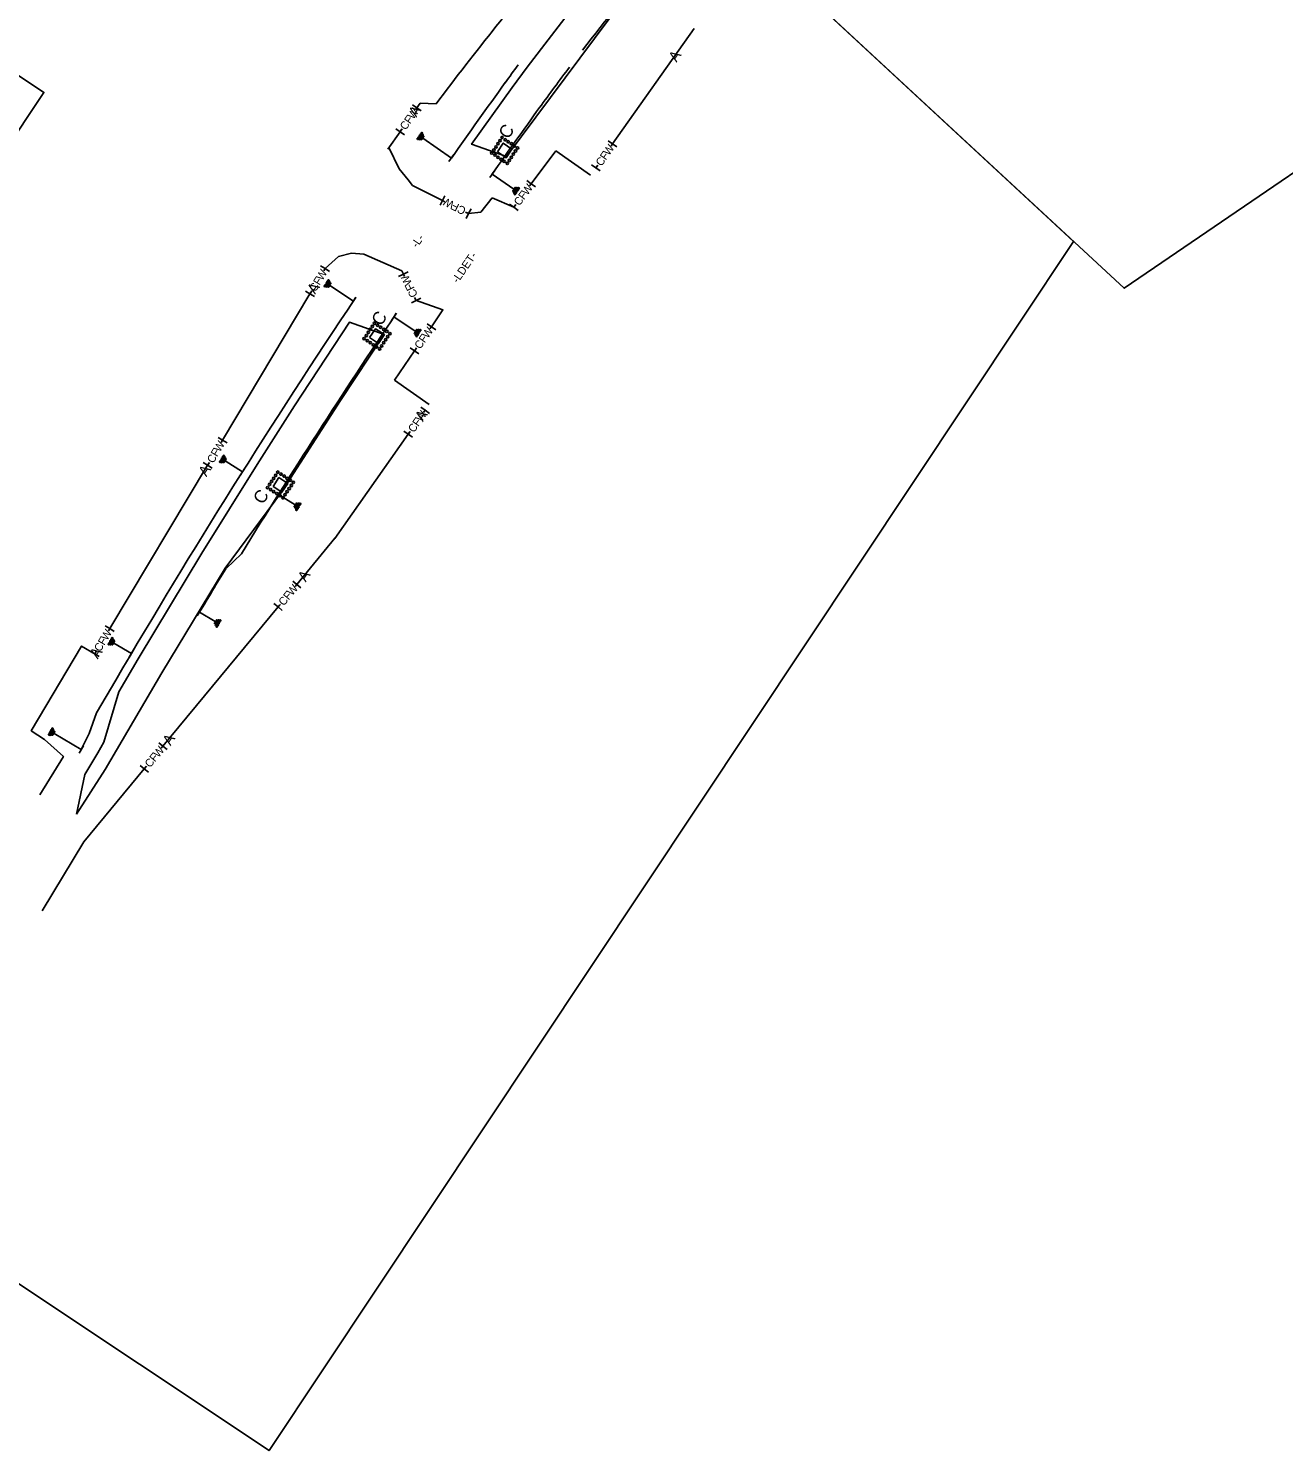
# Model space of a CAD drawing. Extents: x 2357856 to 2382083, y 331121 to 347536.
# Drawn here: x 2379985 to 2381167, y 331121 to 332460 of the extents above; entities that cross this region are included whole.
import ezdxf

# ---------------------------------------------------------------- set-up
doc = ezdxf.new("R2010")
doc.units = 0
for name, color, linetype in [('Coir Fiber Wattle Both CELL', 7, 'Continuous'), ('Default', 7, 'Continuous'), ('E_NCDOT_Vertical_Profile_Ground_Line', 7, 'Continuous'), ('Matting and PSRM Summary Sheet CELL', 7, 'Continuous'), ('Old_Level_12', 7, 'Continuous'), ('P_NCDOT_Horizontal_Alignment_Tick_Small', 7, 'Continuous'), ('Scratch_Level_6', 7, 'Continuous'), ('Scratch_Level_7', 7, 'Continuous'), ('Sheet Data Field CELL', 7, 'Continuous'), ('Sheet_Named_Boundary', 7, 'Continuous'), ('Sheet_Title_Data_Points_CELL', 7, 'Continuous')]:
    doc.layers.add(name, color=color, linetype=linetype)

msp = doc.modelspace()

# ---------------------------------------------------------------- linework, layer by layer
at = {"layer": 'Coir Fiber Wattle Both CELL'}
for p, q in [((2380185.4, 331965.1), (2380170.9, 331951)), ((2380067, 331846), (2380048.9, 331815.1)), ((2380048.9, 331815.1), (2380041.9, 331795.8)), ((2380041.9, 331795.8), (2380034.5, 331780.7))]:
    msp.add_line(p, q, dxfattribs=at)
for centre, radius, start, end in [((2382124.6, 331188.5), 2045, 139.2636, 142.294), ((2382124.6, 331188.5), 2085, 143.6143, 144.1843), ((2382124.6, 331188.5), 2045, 142.8535, 144.1843), ((2386191.3, 328253.9), 7100, 144.18428, 144.88815), ((2386191.3, 328253.9), 7060, 144.18428, 144.8082), ((2386191.3, 328253.9), 7100, 146.17166, 149.60684), ((2386191.3, 328253.9), 7060, 146.10116, 148.28685), ((2386191.3, 328253.9), 7065, 148.44639, 148.83551)]:
    msp.add_arc(centre, radius, start, end, dxfattribs=at)
at = {"layer": 'Default'}
for points in [[(2380245.4, 332929.7), (2381505.4, 333788.6), (2382082.8, 332941.6), (2381016.8, 332215)], [(2379358.1, 331688.3), (2380202.9, 332957.9), (2380245.4, 332929.7), (2380969.1, 332259.1), (2380211.5, 331120.5)]]:
    msp.add_lwpolyline(points, close=True, dxfattribs=at)
at = {"layer": 'Matting and PSRM Summary Sheet CELL'}
for p, q in [((2380350.7, 332385), (2380346.6, 332387.9)), ((2380349.3, 332383), (2380350.7, 332385)), ((2380350.7, 332385), (2380354.8, 332382.2)), ((2380334.9, 332362.5), (2380330.8, 332365.3)), ((2380334.9, 332362.5), (2380336.3, 332364.5)), ((2380334.9, 332362.5), (2380339, 332359.6)), ((2380335.3, 332363.1), (2380336.8, 332365.1)), ((2380535.1, 332350.9), (2380531, 332353.8)), ((2380533.7, 332348.9), (2380535.1, 332350.9)), ((2380535.1, 332350.9), (2380539.2, 332348.1)), ((2380519.2, 332328.4), (2380515.1, 332331.3)), ((2380519.2, 332328.4), (2380520.7, 332330.4)), ((2380519.2, 332328.4), (2380523.3, 332325.5)), ((2380519.7, 332329), (2380521.1, 332331.1)), ((2380458.4, 332313.5), (2380454.4, 332316.4)), ((2380456.9, 332311.4), (2380458.4, 332313.5)), ((2380458.4, 332313.5), (2380462.4, 332310.5)), ((2380374.8, 332297.7), (2380372.5, 332293.2)), ((2380374.8, 332297.7), (2380377, 332302.1)), ((2380377, 332296.5), (2380374.8, 332297.7)), ((2380398.7, 332285.7), (2380396.5, 332286.8)), ((2380399.4, 332285.3), (2380397.2, 332286.4)), ((2380399.4, 332285.3), (2380397.2, 332280.8)), ((2380399.4, 332285.3), (2380401.7, 332289.8)), ((2380442, 332291.3), (2380438, 332294.3)), ((2380442, 332291.3), (2380443.5, 332293.3)), ((2380442, 332291.3), (2380446, 332288.3)), ((2380442.5, 332291.9), (2380444, 332293.9)), ((2380264.2, 332233.5), (2380259.9, 332236.1)), ((2380262.9, 332231.3), (2380264.2, 332233.5)), ((2380264.2, 332233.5), (2380268.5, 332230.9)), ((2380338, 332228.3), (2380333.5, 332226.1)), ((2380338, 332228.3), (2380342.5, 332230.4)), ((2380339.1, 332226), (2380338, 332228.3)), ((2380250, 332209.9), (2380245.7, 332212.4)), ((2380250, 332209.9), (2380251.3, 332212)), ((2380250, 332209.9), (2380254.3, 332207.3)), ((2380250.4, 332210.5), (2380251.7, 332212.7)), ((2380350, 332203.4), (2380345.5, 332201.2)), ((2380349.7, 332204.1), (2380348.6, 332206.4)), ((2380350, 332203.4), (2380348.9, 332205.7)), ((2380350, 332203.4), (2380354.5, 332205.6)), ((2380364.4, 332178.8), (2380360.4, 332181.6)), ((2380363, 332176.7), (2380364.4, 332178.8)), ((2380364.4, 332178.8), (2380368.5, 332175.9)), ((2380348.6, 332156.2), (2380344.5, 332159.1)), ((2380348.6, 332156.2), (2380350, 332158.2)), ((2380348.6, 332156.2), (2380352.6, 332153.3)), ((2380349, 332156.8), (2380350.5, 332158.9)), ((2380358.4, 332100.1), (2380354.3, 332103)), ((2380356.9, 332098.1), (2380358.4, 332100.1)), ((2380358.4, 332100.1), (2380362.5, 332097.2)), ((2380167.7, 332072), (2380163.4, 332074.6)), ((2380166.4, 332069.9), (2380167.7, 332072)), ((2380167.7, 332072), (2380172, 332069.4)), ((2380342.5, 332077.6), (2380338.4, 332080.4)), ((2380342.5, 332077.6), (2380343.9, 332079.6)), ((2380342.5, 332077.6), (2380346.6, 332074.7)), ((2380343, 332078.2), (2380344.4, 332080.2)), ((2380153.6, 332048.3), (2380149.3, 332050.9)), ((2380153.6, 332048.3), (2380154.9, 332050.5)), ((2380153.6, 332048.3), (2380157.9, 332045.7)), ((2380154, 332049), (2380155.3, 332051.1)), ((2380237.5, 331936.1), (2380233.7, 331939.3)), ((2380235.9, 331934.2), (2380237.5, 331936.1)), ((2380237.5, 331936.1), (2380241.4, 331932.9)), ((2380219.9, 331914.9), (2380216.1, 331918.1)), ((2380219.9, 331914.9), (2380221.5, 331916.8)), ((2380219.9, 331914.9), (2380223.8, 331911.7)), ((2380220.5, 331915.5), (2380222.1, 331917.4)), ((2380061.4, 331894.5), (2380057.1, 331897)), ((2380060.1, 331892.3), (2380061.4, 331894.5)), ((2380061.4, 331894.5), (2380065.7, 331891.9)), ((2380047.2, 331870.8), (2380043, 331873.4)), ((2380047.2, 331870.8), (2380048.5, 331873)), ((2380047.2, 331870.8), (2380051.5, 331868.2)), ((2380047.7, 331871.5), (2380049, 331873.6)), ((2380111.5, 331783.8), (2380107.7, 331787)), ((2380109.9, 331781.8), (2380111.5, 331783.8)), ((2380111.5, 331783.8), (2380115.4, 331780.6)), ((2380093.9, 331762.5), (2380090.1, 331765.7)), ((2380093.9, 331762.5), (2380095.5, 331764.4)), ((2380093.9, 331762.5), (2380097.8, 331759.3)), ((2380094.5, 331763.1), (2380096.1, 331765))]:
    msp.add_line(p, q, dxfattribs=at)
at = {"layer": 'Old_Level_12'}
for p, q in [((2380356.4, 332356.4), (2380383.3, 332337.6)), ((2380385.6, 332340.9), (2380380.9, 332334.3)), ((2380419.3, 332319.3), (2380424, 332326)), ((2380441.9, 332308.5), (2380421.7, 332322.6)), ((2380268.7, 332217.8), (2380290.9, 332203)), ((2380293.2, 332206.4), (2380288.7, 332199.6)), ((2380326.8, 332184.7), (2380331.4, 332191.5)), ((2380349.1, 332174.7), (2380329.1, 332188.1)), ((2380170.2, 332052.5), (2380186.5, 332042.3)), ((2380188.6, 332045.7), (2380184.3, 332038.8)), ((2380218.1, 332017.5), (2380222.5, 332024.4)), ((2380236, 332011.1), (2380220.3, 332020.9)), ((2380143.6, 331906.5), (2380147.8, 331913.5)), ((2380160.8, 331901.2), (2380145.9, 331910)), ((2380065.2, 331880.9), (2380081.8, 331871.1)), ((2380083.9, 331874.6), (2380079.8, 331867.6)), ((2380008.9, 331795.7), (2380034.5, 331780.7)), ((2380036.7, 331784.2), (2380032.6, 331777.1))]:
    msp.add_line(p, q, dxfattribs=at)
for centre, major_axis in [((2380351.7, 332355.8), (0.613, -0.43)), ((2380352.6, 332357), (0.613, -0.43)), ((2380353.3, 332355.6), (0.613, -0.43)), ((2380353.5, 332358.5), (0.613, -0.43)), ((2380354.2, 332357.1), (0.613, -0.43)), ((2380354.4, 332359.8), (0.613, -0.43)), ((2380354.9, 332355.6), (0.613, -0.43)), ((2380355, 332358.3), (0.613, -0.43)), ((2380355.3, 332361.1), (0.613, -0.43)), ((2380355.8, 332356.9), (0.613, -0.43)), ((2380355.9, 332359.6), (0.613, -0.43)), ((2380356.6, 332358.1), (0.613, -0.43)), ((2380442.5, 332308.1), (-0.613, 0.431)), ((2380443.3, 332309.3), (-0.613, 0.431)), ((2380444.1, 332307.8), (-0.613, 0.431)), ((2380444.9, 332309.3), (-0.613, 0.431)), ((2380445.7, 332307.9), (-0.613, 0.431)), ((2380446.5, 332309.1), (-0.613, 0.431)), ((2380441.7, 332306.8), (-0.613, 0.431)), ((2380442.3, 332305.3), (-0.613, 0.431)), ((2380443, 332303.8), (-0.613, 0.431)), ((2380443.2, 332306.6), (-0.613, 0.431)), ((2380443.9, 332305.1), (-0.613, 0.431)), ((2380444.7, 332306.4), (-0.613, 0.431)), ((2380264.1, 332217), (0.624, -0.415)), ((2380264.9, 332218.3), (0.624, -0.415)), ((2380265.7, 332216.9), (0.624, -0.415)), ((2380265.8, 332219.8), (0.624, -0.415)), ((2380266.5, 332218.4), (0.624, -0.415)), ((2380266.6, 332221.1), (0.624, -0.415)), ((2380267.3, 332216.9), (0.624, -0.415)), ((2380267.3, 332219.6), (0.624, -0.415)), ((2380267.5, 332222.4), (0.624, -0.415)), ((2380268.2, 332220.9), (0.624, -0.415)), ((2380268.1, 332218.2), (0.624, -0.415)), ((2380268.9, 332219.5), (0.624, -0.415)), ((2380349.7, 332174.3), (-0.623, 0.416)), ((2380350.6, 332175.6), (-0.623, 0.416)), ((2380351.3, 332174.1), (-0.623, 0.416)), ((2380352.2, 332175.6), (-0.623, 0.416)), ((2380352.9, 332174.3), (-0.623, 0.416)), ((2380353.8, 332175.5), (-0.623, 0.416)), ((2380349, 332173.1), (-0.623, 0.416)), ((2380349.6, 332171.6), (-0.623, 0.416)), ((2380350.3, 332170.1), (-0.623, 0.416)), ((2380350.5, 332172.9), (-0.623, 0.416)), ((2380351.2, 332171.4), (-0.623, 0.416)), ((2380352, 332172.7), (-0.623, 0.416)), ((2380167.2, 332054.5), (0.634, -0.4)), ((2380168, 332055.8), (0.634, -0.4)), ((2380168.7, 332054.3), (0.634, -0.4)), ((2380168.8, 332057.1), (0.634, -0.4)), ((2380169.6, 332055.6), (0.634, -0.4)), ((2380170.3, 332054.2), (0.634, -0.4)), ((2380165.5, 332051.6), (0.634, -0.4)), ((2380166.4, 332052.9), (0.634, -0.4)), ((2380167.1, 332051.5), (0.634, -0.4)), ((2380167.9, 332053.1), (0.634, -0.4)), ((2380168.7, 332051.6), (0.634, -0.4)), ((2380169.5, 332052.9), (0.634, -0.4)), ((2380235.9, 332009.4), (-0.634, 0.398)), ((2380236.6, 332010.7), (-0.634, 0.398)), ((2380236.6, 332008), (-0.634, 0.398)), ((2380237.3, 332006.5), (-0.634, 0.398)), ((2380237.4, 332012), (-0.634, 0.398)), ((2380237.5, 332009.3), (-0.634, 0.398)), ((2380238.2, 332007.8), (-0.634, 0.398)), ((2380238.2, 332010.5), (-0.634, 0.398)), ((2380239, 332012.1), (-0.634, 0.398)), ((2380239, 332009.1), (-0.634, 0.398)), ((2380239.8, 332010.7), (-0.634, 0.398)), ((2380240.6, 332012), (-0.634, 0.398)), ((2380160.7, 331899.5), (-0.645, 0.381)), ((2380161.4, 331900.8), (-0.645, 0.381)), ((2380161.5, 331898.1), (-0.645, 0.381)), ((2380162.2, 331902.1), (-0.645, 0.381)), ((2380162.2, 331896.6), (-0.645, 0.381)), ((2380162.3, 331899.4), (-0.645, 0.381)), ((2380163, 331900.7), (-0.645, 0.381)), ((2380163, 331898), (-0.645, 0.381)), ((2380163.8, 331902.2), (-0.645, 0.381)), ((2380163.8, 331899.3), (-0.645, 0.381)), ((2380164.6, 331900.9), (-0.645, 0.381)), ((2380165.4, 331902.2), (-0.645, 0.381)), ((2380060.6, 331879.8), (0.645, -0.38)), ((2380061.4, 331881.2), (0.645, -0.38)), ((2380062.2, 331882.7), (0.645, -0.38)), ((2380062.2, 331879.8), (0.645, -0.38)), ((2380063, 331884.1), (0.645, -0.38)), ((2380063, 331881.4), (0.645, -0.38)), ((2380063.8, 331885.4), (0.645, -0.38)), ((2380063.7, 331882.6), (0.645, -0.38)), ((2380063.8, 331879.9), (0.645, -0.38)), ((2380064.5, 331884), (0.645, -0.38)), ((2380064.6, 331881.3), (0.645, -0.38)), ((2380065.3, 331882.6), (0.645, -0.38)), ((2380006.6, 331798.9), (0.645, -0.38)), ((2380007.4, 331800.3), (0.645, -0.38)), ((2380008.2, 331798.9), (0.645, -0.38)), ((2380004.3, 331794.7), (0.645, -0.38)), ((2380005.1, 331796), (0.645, -0.38)), ((2380005.8, 331797.6), (0.645, -0.38)), ((2380005.9, 331794.7), (0.645, -0.38)), ((2380006.6, 331796.2), (0.645, -0.38)), ((2380007.4, 331797.5), (0.645, -0.38)), ((2380007.5, 331794.8), (0.645, -0.38)), ((2380008.2, 331796.1), (0.645, -0.38)), ((2380008.9, 331797.4), (0.645, -0.38))]:
    msp.add_ellipse(centre, major_axis=major_axis, ratio=0.927398, dxfattribs=at)
at = {"layer": 'Scratch_Level_6'}
for p, q in [((2380431.6, 332357.8), (2380431.5, 332357.8)), ((2380434.5, 332355.9), (2380434.4, 332355.9)), ((2380437.4, 332353.9), (2380437.4, 332354)), ((2380311.4, 332183), (2380311.3, 332183.1)), ((2380314.3, 332181.1), (2380314.2, 332181.1)), ((2380317.2, 332179.2), (2380317.1, 332179.2)), ((2380220.4, 332042.8), (2380220.3, 332042.9)), ((2380223.3, 332040.9), (2380223.2, 332041)), ((2380226.2, 332039), (2380226.2, 332039))]:
    msp.add_line(p, q, dxfattribs=at)
for points in [[(2380426.5, 332343.4), (2380432, 332351.7), (2380440.3, 332346.1), (2380434.8, 332337.8)], [(2380306.2, 332168.6), (2380311.8, 332176.9), (2380320.1, 332171.4), (2380314.5, 332163.1)], [(2380215.3, 332028.4), (2380220.8, 332036.7), (2380229.1, 332031.2), (2380223.6, 332022.9)]]:
    msp.add_lwpolyline(points, close=True, dxfattribs=at)
for centre in [(2380425.1, 332348.1), (2380427.1, 332351.1), (2380429, 332354), (2380439.7, 332351.1), (2380442.6, 332349.1), (2380421.2, 332342.3), (2380423.2, 332345.2), (2380424.2, 332340.4), (2380427.1, 332338.4), (2380430, 332336.5), (2380432.9, 332334.6), (2380437.8, 332335.5), (2380439.7, 332338.4), (2380441.6, 332341.4), (2380443.6, 332344.3), (2380445.5, 332347.2), (2380435.8, 332332.6), (2380304.9, 332173.4), (2380306.8, 332176.3), (2380308.8, 332179.2), (2380319.5, 332176.3), (2380322.4, 332174.4), (2380301, 332167.6), (2380303, 332170.5), (2380303.9, 332165.6), (2380306.8, 332163.7), (2380309.8, 332161.7), (2380317.5, 332160.8), (2380319.5, 332163.7), (2380321.4, 332166.6), (2380323.3, 332169.5), (2380325.3, 332172.4), (2380312.7, 332159.8), (2380315.6, 332157.9), (2380210, 332027.4), (2380212, 332030.3), (2380213.9, 332033.2), (2380215.9, 332036.1), (2380217.8, 332039), (2380228.5, 332036.1), (2380230.4, 332026.4), (2380231.4, 332034.2), (2380232.4, 332029.3), (2380234.3, 332032.2), (2380213, 332025.4), (2380215.9, 332023.5), (2380218.8, 332021.6), (2380221.7, 332019.6), (2380224.6, 332017.7), (2380226.6, 332020.6), (2380228.5, 332023.5)]:
    msp.add_circle(centre, 1.12, dxfattribs=at)
for centre, start, end in [((2380430.9, 332356.9), 58.8724, 53.8495), ((2380433.9, 332354.9), 58.5359, 54.186), ((2380436.8, 332353), 58.1368, 54.5852), ((2380310.7, 332182.1), 58.8724, 53.8495), ((2380313.6, 332180.2), 58.5359, 54.186), ((2380316.5, 332178.3), 58.1368, 54.5852), ((2380219.7, 332041.9), 58.8724, 53.8495), ((2380222.7, 332040), 58.5359, 54.186), ((2380225.6, 332038.1), 58.1368, 54.5852)]:
    msp.add_arc(centre, 1.12, start, end, dxfattribs=at)
at = {"layer": 'Scratch_Level_7'}
msp.add_lwpolyline([(2379956.4, 332428.1), (2379762.4, 332136.6), (2379805.4, 332108), (2379999.4, 332399.5)], close=True, dxfattribs=at)
at = {"layer": 'Sheet Data Field CELL'}
msp.add_lwpolyline([(2380503.7, 332487.2), (2380454.6, 332423.4), (2380440.4, 332404), (2380402.2, 332350.6), (2380435.1, 332339), (2380531.8, 332468.7)], dxfattribs=at)
msp.add_lwpolyline([(2380030, 331719.7), (2380038, 331757), (2380050.2, 331777.7), (2380055.9, 331787.5), (2380069.9, 331835), (2380088.2, 331866.1), (2380148.1, 331965.6), (2380200.3, 332049.1), (2380235.5, 332104.2), (2380287.2, 332183), (2380319.8, 332171.5), (2380278.9, 332109.5), (2380223.3, 332022.9), (2380170, 331951.5), (2380110.5, 331852.8), (2380057.1, 331761.8)], close=True, dxfattribs=at)
at = {"layer": 'Sheet_Named_Boundary'}
for p, q in [((2380535.1, 332350.9), (2380611.8, 332459.7)), ((2380353.7, 332389.3), (2380350.7, 332385)), ((2380368.9, 332388.7), (2380353.7, 332389.3)), ((2380334.9, 332362.5), (2380323.4, 332346.1)), ((2380481.5, 332344.4), (2380458.4, 332313.5)), ((2380481.5, 332344.4), (2380514.3, 332321.4)), ((2380374.8, 332297.7), (2380346.5, 332311.8)), ((2380442, 332291.3), (2380421.7, 332300.3)), ((2380167.7, 332072), (2380250, 332209.9)), ((2380329.6, 332128.6), (2380348.6, 332156.2)), ((2380362.3, 332105.7), (2380329.6, 332128.6)), ((2380273.4, 331979.5), (2380342.5, 332077.6)), ((2380061.4, 331894.5), (2380153.6, 332048.3)), ((2380237.5, 331936.1), (2380273.4, 331979.6)), ((2380111.5, 331783.8), (2380219.9, 331914.9))]:
    msp.add_line(p, q, dxfattribs=at)
for points in [[(2380324.3, 332347.5), (2380334, 332327.4), (2380342.6, 332317.1), (2380346.5, 332311.8)], [(2380399.4, 332285.3), (2380410.9, 332286.8), (2380421.7, 332300.3)], [(2380338, 332228.3), (2380336.4, 332231.5), (2380300.6, 332247.3), (2380289.2, 332248), (2380277, 332244.9), (2380264.2, 332233.5)], [(2380364.4, 332178.8), (2380375.3, 332194.6), (2380349.3, 332203.7)], [(2379995.5, 331738.1), (2380017.7, 331774.2), (2379999.8, 331790.2), (2379987.5, 331798.4), (2380034.9, 331878.1), (2380047.6, 331870.6)], [(2379997.8, 331628.9), (2380037, 331693.6), (2380093.9, 331762.5)]]:
    msp.add_lwpolyline(points, dxfattribs=at)
for centre, radius, start, end in [((2382983.2, 330424), 3270.3, 139.851, 143.0741), ((2380368.9, 332388.7), 0.0000000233, 179.7652, 180.1182)]:
    msp.add_arc(centre, radius, start, end, dxfattribs=at)

# ---------------------------------------------------------------- texts
at = {"layer": 'E_NCDOT_Vertical_Profile_Ground_Line'}
for p in [(2380436.7, 332354.7), (2380316.9, 332178.7), (2380205.5, 332010.7)]:
    msp.add_text('C', height=12, rotation=56.361, dxfattribs=at).set_placement(p)
at = {"layer": 'Matting and PSRM Summary Sheet CELL'}
for s, rotation, p in [('F', 54.9145, (2380344.3, 332369.2)), ('W', 54.9145, (2380347.4, 332373.5)), ('C', 54.9145, (2380340.2, 332363.4)), ('W', 54.829, (2380531.7, 332339.4)), ('C', 54.829, (2380524.6, 332329.3)), ('F', 54.829, (2380528.7, 332335.1)), ('W', 53.3883, (2380454.8, 332302)), ('W', 153.3742, (2380386.7, 332296)), ('C', 53.3883, (2380447.4, 332292.1)), ('F', 53.3883, (2380451.6, 332297.8)), ('F', 153.3742, (2380391.3, 332293.7)), ('C', 153.3742, (2380397.7, 332290.5)), ('W', 58.9143, (2380261.7, 332221.7)), ('C', 58.9143, (2380255.3, 332211.1)), ('F', 58.9143, (2380259, 332217.3)), ('W', 115.8148, (2380346.4, 332219.7)), ('F', 115.8148, (2380348.7, 332215)), ('C', 115.8148, (2380351.8, 332208.6)), ('W', 54.829, (2380361.1, 332167.2)), ('C', 54.829, (2380353.9, 332157.1)), ('F', 54.829, (2380358, 332163)), ('W', 54.829, (2380355, 332088.6)), ('C', 54.829, (2380347.9, 332078.5)), ('F', 54.829, (2380352, 332084.3)), ('W', 59.2049, (2380165.2, 332060.2)), ('C', 59.2049, (2380158.9, 332049.6)), ('F', 59.2049, (2380162.5, 332055.8)), ('W', 50.4117, (2380233.3, 331924.9)), ('C', 50.4117, (2380225.4, 331915.4)), ('F', 50.4117, (2380229.9, 331920.9)), ('W', 59.096, (2380058.9, 331882.7)), ('C', 59.096, (2380052.5, 331872.1)), ('F', 59.096, (2380056.2, 331878.2)), ('F', 50.4117, (2380103.9, 331768.5)), ('W', 50.4117, (2380107.3, 331772.5)), ('C', 50.4117, (2380099.4, 331763))]:
    msp.add_text(s, height=7.54, rotation=rotation, dxfattribs=at).set_placement(p)
at = {"layer": 'P_NCDOT_Horizontal_Alignment_Tick_Small'}
for p in [(2380595.3, 332427.4), (2380350.3, 332375.5), (2380254.8, 332208.9), (2380356.3, 332088.9), (2380152.4, 332037.1), (2380246, 331937.9), (2380050, 331865.3), (2380118.6, 331783.8)]:
    msp.add_text('A', height=10, rotation=56.361, dxfattribs=at).set_placement(p)
at = {"layer": 'Sheet_Title_Data_Points_CELL'}
for s, p in [('-L-', (2380350.9, 332252.5)), ('-LDET-', (2380389.3, 332219.3))]:
    msp.add_text(s, height=7.5, rotation=55.5905, dxfattribs=at).set_placement(p)

doc.saveas('drawing.dxf')
